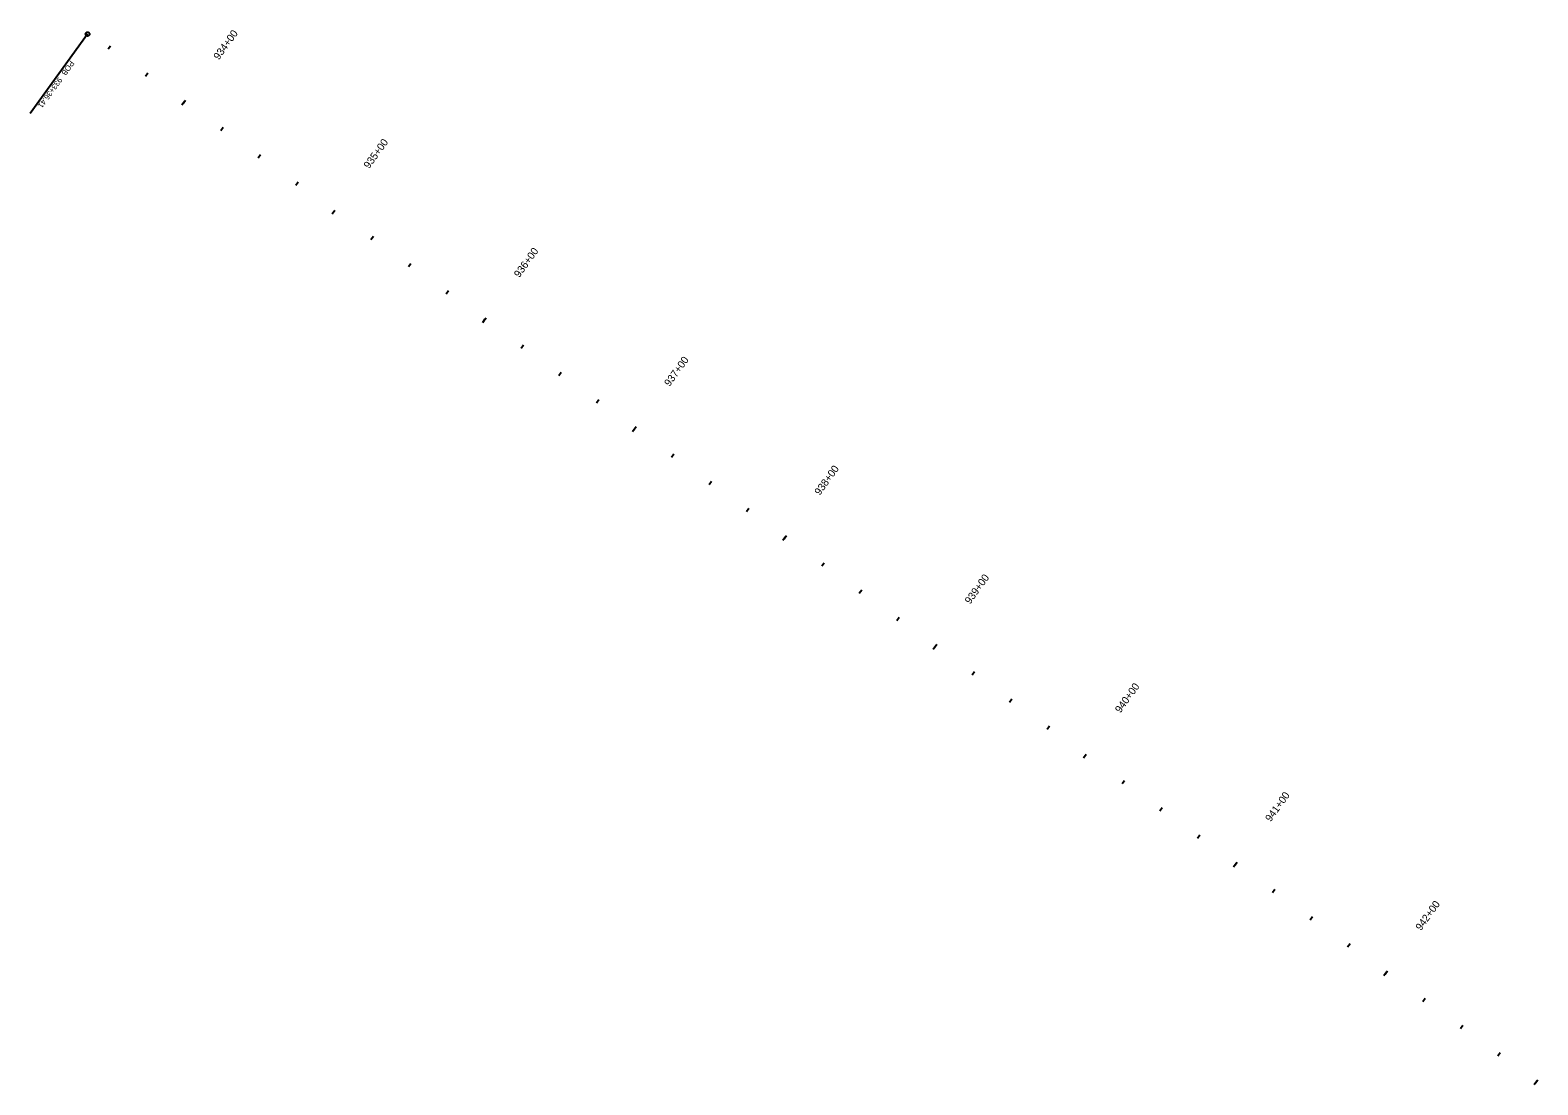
# Model space of a CAD drawing. Extents: x 14311466 to 14314811, y 8682098 to 8684603.
# Drawn here: x 14311466 to 14312278, y 8684035 to 8684603 of the extents above; entities that cross this region are included whole.
import ezdxf

# ---------------------------------------------------------------- set-up
doc = ezdxf.new("R2010")
doc.units = 0
for name, color, linetype in [('TextAlignment', 7, 'Continuous'), ('TextAlignmentLrg', 7, 'Continuous'), ('TextAlignmentSml', 7, 'Continuous')]:
    doc.layers.add(name, color=color, linetype=linetype)

msp = doc.modelspace()

# ---------------------------------------------------------------- linework, layer by layer
at = {"layer": 'TextAlignment'}
for p in [(14311496.53, 8684600.82), (14311465.57, 8684558.05)]:
    msp.add_line(p, (14311465.57, 8684558.05), dxfattribs=at)
msp.add_circle((14311496.53, 8684600.82), 1.07, dxfattribs=at)
at = {"layer": 'TextAlignmentLrg'}
for p, q in [((14311548.04, 8684563.52), (14311549.32, 8684565.29)), ((14311629.75, 8684505.87), (14311628.32, 8684503.89)), ((14311710.03, 8684446.23), (14311711.31, 8684448)), ((14311791.03, 8684387.59), (14311792.31, 8684389.35)), ((14311872.03, 8684328.94), (14311873.31, 8684330.71)), ((14311953.03, 8684270.29), (14311954.31, 8684272.06)), ((14312034.74, 8684212.64), (14312033.31, 8684210.66)), ((14312115.02, 8684153), (14312116.3, 8684154.77)), ((14312196.02, 8684094.36), (14312197.3, 8684096.13)), ((14312277.02, 8684035.71), (14312278.3, 8684037.48))]:
    msp.add_line(p, q, dxfattribs=at)
at = {"layer": 'TextAlignmentSml'}
for p, q in [((14311507.54, 8684592.85), (14311508.82, 8684594.61)), ((14311527.79, 8684578.18), (14311529.07, 8684579.95)), ((14311548.76, 8684564.51), (14311547.32, 8684562.53)), ((14311568.29, 8684548.86), (14311569.57, 8684550.63)), ((14311588.54, 8684534.2), (14311589.82, 8684535.97)), ((14311608.79, 8684519.54), (14311610.07, 8684521.31)), ((14311629.75, 8684505.87), (14311628.32, 8684503.89)), ((14311649.29, 8684490.22), (14311650.57, 8684491.98)), ((14311669.54, 8684475.55), (14311670.82, 8684477.32)), ((14311689.78, 8684460.89), (14311691.07, 8684462.66)), ((14311710.75, 8684447.22), (14311709.32, 8684445.24)), ((14311730.28, 8684431.57), (14311731.56, 8684433.34)), ((14311750.53, 8684416.91), (14311751.81, 8684418.68)), ((14311770.78, 8684402.25), (14311772.06, 8684404.02)), ((14311791.75, 8684388.58), (14311790.31, 8684386.59)), ((14311811.28, 8684372.92), (14311812.56, 8684374.69)), ((14311831.53, 8684358.26), (14311832.81, 8684360.03)), ((14311851.78, 8684343.6), (14311853.06, 8684345.37)), ((14311872.75, 8684329.93), (14311871.31, 8684327.95)), ((14311892.28, 8684314.28), (14311893.56, 8684316.05)), ((14311912.53, 8684299.62), (14311913.81, 8684301.39)), ((14311932.78, 8684284.96), (14311934.06, 8684286.72)), ((14311953.75, 8684271.28), (14311952.31, 8684269.3)), ((14311973.28, 8684255.63), (14311974.56, 8684257.4)), ((14311993.53, 8684240.97), (14311994.81, 8684242.74)), ((14312013.78, 8684226.31), (14312015.06, 8684228.08)), ((14312034.74, 8684212.64), (14312033.31, 8684210.66)), ((14312054.28, 8684196.99), (14312055.56, 8684198.76)), ((14312074.53, 8684182.32), (14312075.81, 8684184.09)), ((14312094.77, 8684167.66), (14312096.06, 8684169.43)), ((14312115.74, 8684153.99), (14312114.31, 8684152.01)), ((14312135.27, 8684138.34), (14312136.55, 8684140.11)), ((14312155.52, 8684123.68), (14312156.8, 8684125.45)), ((14312175.77, 8684109.02), (14312177.05, 8684110.79)), ((14312196.74, 8684095.35), (14312195.3, 8684093.36)), ((14312216.27, 8684079.69), (14312217.55, 8684081.46)), ((14312236.52, 8684065.03), (14312237.8, 8684066.8)), ((14312256.77, 8684050.37), (14312258.05, 8684052.14)), ((14312277.74, 8684036.7), (14312276.3, 8684034.72))]:
    msp.add_line(p, q, dxfattribs=at)

# ---------------------------------------------------------------- texts
at = {"layer": 'TextAlignment'}
for s, p in [('POB ', (14311487.21, 8684586.82)), ('933+36.41', (14311480.71, 8684577.84))]:
    msp.add_text(s, height=3, rotation=234.09397, dxfattribs=at).set_placement(p)
at = {"layer": 'TextAlignmentLrg'}
for s, p in [('935+00', (14311648.25, 8684528)), ('940+00', (14312053.24, 8684234.77))]:
    msp.add_text(s, height=4.008, rotation=54.09397, dxfattribs=at).set_placement(p)
at = {"layer": 'TextAlignmentSml'}
for s, p in [('934+00', (14311567.26, 8684586.65)), ('935+00', (14311648.25, 8684528)), ('936+00', (14311729.25, 8684469.35)), ('937+00', (14311810.25, 8684410.71)), ('938+00', (14311891.25, 8684352.06)), ('939+00', (14311972.25, 8684293.42)), ('940+00', (14312053.24, 8684234.77)), ('941+00', (14312134.24, 8684176.13)), ('942+00', (14312215.24, 8684117.48))]:
    msp.add_text(s, height=4.008, rotation=54.09397, dxfattribs=at).set_placement(p)

doc.saveas('drawing.dxf')
